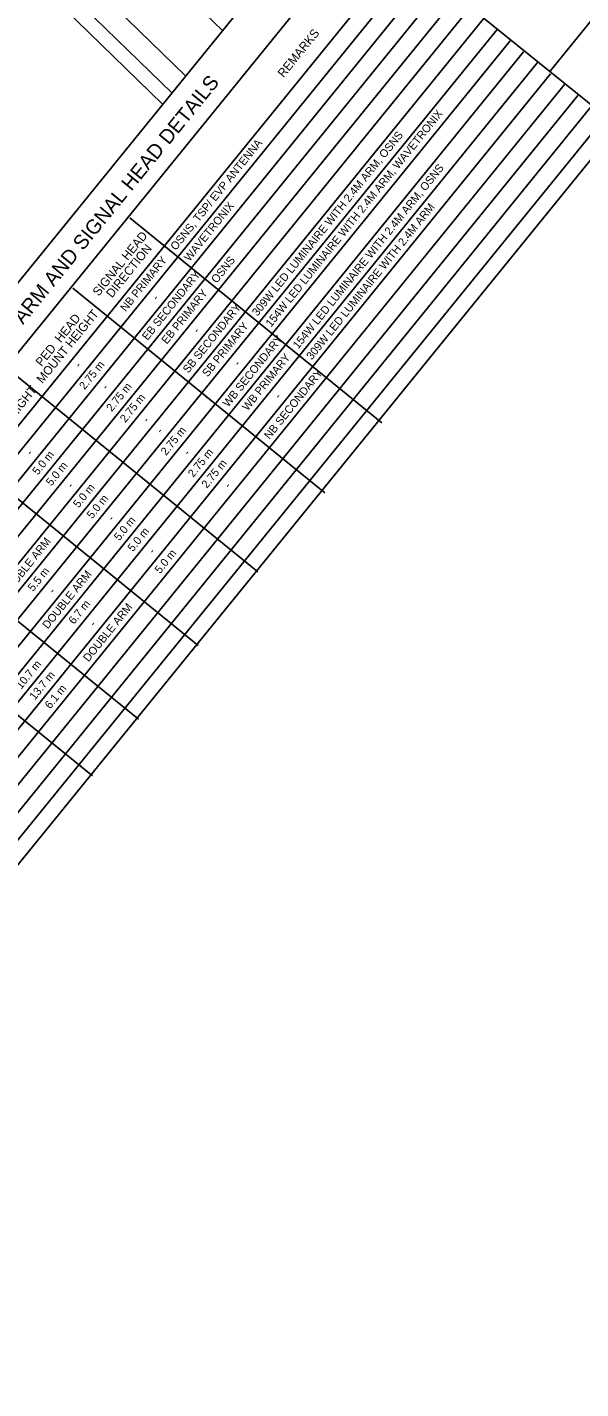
# Model space of a CAD drawing. Extents: x 592613 to 600223, y 4837996 to 4840103.
# Drawn here: x 593036.6 to 593074.7, y 4839186.1 to 4839279.7 of the extents above; entities that cross this region are included whole.
import ezdxf

# ---------------------------------------------------------------- set-up
doc = ezdxf.new("R2010")
doc.units = 0
for name, color, linetype in [('ENG_BORDER', 7, 'Continuous'), ('ENG_KILLSTRIP', 7, 'Continuous'), ('ENG_SIDEWALK', 7, 'Continuous'), ('ENG_TITLEBLOCK', 7, 'Continuous'), ('ENG_TX_TITLEBLOCK', 7, 'Continuous'), ('Level 31', 7, 'Continuous'), ('Level 54', 7, 'Continuous'), ('ROW_ENG_ROW', 7, 'Continuous')]:
    doc.layers.add(name, color=color, linetype=linetype)

msp = doc.modelspace()

# ---------------------------------------------------------------- linework, layer by layer
at = {"layer": 'ENG_BORDER'}
for p, q in [((593077.324, 4839272.823), (593057.566, 4839288.798)), ((593017.004, 4839234.009), (593059.952, 4839286.868)), ((593043.511, 4839266.633), (593043.622, 4839266.769))]:
    msp.add_line(p, q, dxfattribs=at)
msp.add_lwpolyline([(593006.685, 4839186.123), (593132.065, 4839340.435), (593027.682, 4839425.246)], dxfattribs=at)
at = {"layer": 'ENG_KILLSTRIP'}
msp.add_line((593050.039, 4839279.514), (593045.892, 4839283.543), dxfattribs=at)
at = {"layer": 'ENG_SIDEWALK'}
for p, q in [((593047.51, 4839276.395), (593025.434, 4839297.841)), ((593046.561, 4839275.225), (593024.799, 4839296.366))]:
    msp.add_line(p, q, dxfattribs=at)
at = {"layer": 'ENG_TITLEBLOCK'}
for p, q in [((593014.678, 4839235.899), (593087.391, 4839325.585)), ((593072.542, 4839276.692), (593083.341, 4839289.983))]:
    msp.add_line(p, q, dxfattribs=at)
at = {"layer": 'Level 31'}
for p, q in [((593019.478, 4839231.999), (593062.405, 4839284.832)), ((593022.481, 4839233.799), (593063.333, 4839284.078)), ((593021.335, 4839230.491), (593064.261, 4839283.324)), ((593022.263, 4839229.736), (593065.161, 4839282.536)), ((593023.19, 4839228.983), (593066.104, 4839281.799)), ((593024.118, 4839228.229), (593067.045, 4839281.062)), ((593025.046, 4839227.475), (593067.959, 4839280.291)), ((593025.974, 4839226.721), (593068.915, 4839279.571)), ((593026.902, 4839225.967), (593069.816, 4839278.782)), ((593027.831, 4839225.212), (593070.744, 4839278.029)), ((593028.759, 4839224.458), (593071.686, 4839277.292)), ((593029.686, 4839223.705), (593072.6, 4839276.52)), ((593030.615, 4839222.951), (593073.542, 4839275.784)), ((593031.543, 4839222.197), (593074.47, 4839275.029)), ((593032.471, 4839221.442), (593075.397, 4839274.276)), ((593033.399, 4839220.689), (593076.325, 4839273.521)), ((593060.998, 4839252.539), (593043.675, 4839266.614)), ((593057.072, 4839247.708), (593039.75, 4839261.782)), ((593052.48, 4839242.276), (593035.156, 4839256.35)), ((593048.369, 4839237.216), (593031.084, 4839251.26)), ((593044.257, 4839232.156), (593026.95, 4839246.219)), ((593041.095, 4839228.264), (593023.773, 4839242.338))]:
    msp.add_line(p, q, dxfattribs=at)
at = {"layer": 'Level 54'}
msp.add_line((593040.993, 4839228.347), (593023.773, 4839242.338), dxfattribs=at)
at = {"layer": 'ROW_ENG_ROW'}
msp.add_line((593045.929, 4839274.445), (593031.168, 4839288.785), dxfattribs=at)

# ---------------------------------------------------------------- texts
at = {"layer": 'ENG_TX_TITLEBLOCK'}
for s, height, rotation, p in [('REMARKS', 0.6, 50.9062, (593054.244, 4839276.225)), ('SIGNAL POLE, MAST ARM AND SIGNAL HEAD DETAILS', 1, 50.9062, (593027.702, 4839248.634)), ('154W LED LUMINAIRE WITH 2.4M ARM, WAVETRONIX', 0.55, 51.14583, (593053.379, 4839259.073)), ('309W LED LUMINAIRE WITH 2.4M ARM, OSNS', 0.55, 51.14583, (593052.444, 4839259.826)), ('OSNS, TSP/ EVP ANTENNA', 0.55, 51.14583, (593046.837, 4839264.343)), ('154W LED LUMINAIRE WITH 2.4M ARM, OSNS', 0.55, 51.14583, (593055.248, 4839257.568)), ('WAVETRONIX', 0.55, 51.14583, (593047.772, 4839263.59)), ('309W LED LUMINAIRE WITH 2.4M ARM', 0.55, 51.14583, (593056.182, 4839256.815)), ('SIGNAL HEAD', 0.6, 50.9062, (593041.527, 4839261.196)), ('DIRECTION', 0.6, 50.9062, (593042.445, 4839261.081)), ('NB PRIMARY', 0.55, 51.14583, (593043.391, 4839260.132)), ('OSNS', 0.55, 51.14583, (593049.641, 4839262.084)), ('EB SECONDARY', 0.55, 51.14583, (593044.885, 4839258.16)), ('-', 0.55, 51.14583, (593045.549, 4839260.898)), ('EB PRIMARY', 0.55, 51.14583, (593046.217, 4839257.901)), ('MOUNT HEIGHT', 0.6, 50.9062, (593037.663, 4839255.195)), ('SB SECONDARY', 0.55, 51.14583, (593047.688, 4839255.901)), ('PED  HEAD', 0.6, 50.9062, (593037.601, 4839256.365)), ('SB PRIMARY', 0.55, 51.14583, (593049.02, 4839255.642)), ('-', 0.55, 51.14583, (593048.353, 4839258.639)), ('WB SECONDARY', 0.55, 51.14583, (593050.434, 4839253.572)), ('WB PRIMARY', 0.55, 51.14583, (593051.767, 4839253.313)), ('-', 0.55, 51.14583, (593040.225, 4839256.261)), ('2.75 m', 0.55, 51.14583, (593040.562, 4839254.766)), ('-', 0.55, 51.14583, (593051.156, 4839256.381)), ('NB SECONDARY', 0.55, 51.14583, (593053.273, 4839251.357)), ('MOUNT HEIGHT', 0.6, 50.9062, (593033.415, 4839249.967)), ('-', 0.55, 51.14583, (593042.094, 4839254.755)), ('2.75 m', 0.55, 51.14583, (593042.431, 4839253.26)), ('2.75 m', 0.55, 51.14583, (593043.365, 4839252.508)), ('-', 0.55, 51.14583, (593053.96, 4839254.122)), ('-', 0.55, 51.14583, (593044.897, 4839252.497)), ('-', 0.55, 51.14583, (593045.832, 4839251.744)), ('2.75 m', 0.55, 51.14583, (593046.169, 4839250.249)), ('2.75 m', 0.55, 51.14583, (593048.038, 4839248.743)), ('-', 0.55, 51.14583, (593036.888, 4839250.246)), ('5.0 m', 0.55, 51.14583, (593037.345, 4839248.9)), ('5.0 m', 0.55, 51.14583, (593038.279, 4839248.148)), ('-', 0.55, 51.14583, (593047.701, 4839250.238)), ('2.75 m', 0.55, 51.14583, (593048.972, 4839247.991)), ('-', 0.55, 51.14583, (593039.692, 4839247.988)), ('5.0 m', 0.55, 51.14583, (593040.148, 4839246.642)), ('-', 0.55, 51.14583, (593050.504, 4839247.98)), ('5.0 m', 0.55, 51.14583, (593041.083, 4839245.889)), ('-', 0.55, 51.14583, (593042.495, 4839245.729)), ('5.0 m', 0.55, 51.14583, (593042.952, 4839244.384)), ('5.0 m', 0.55, 51.14583, (593043.886, 4839243.631)), ('DOUBLE ARM', 0.55, 51.14583, (593035.229, 4839240.578)), ('-', 0.55, 51.14583, (593045.299, 4839243.471)), ('5.0 m', 0.55, 51.14583, (593045.755, 4839242.125)), ('5.5 m', 0.55, 51.14583, (593037.028, 4839240.898)), ('DOUBLE ARM', 0.55, 51.14583, (593038.032, 4839238.32)), ('-', 0.55, 51.14583, (593038.44, 4839240.738)), ('6.7 m', 0.55, 51.14583, (593039.831, 4839238.64)), ('DOUBLE ARM', 0.55, 51.14583, (593040.836, 4839236.061)), ('-', 0.55, 51.14583, (593041.243, 4839238.48)), ('10.7 m', 0.55, 51.14583, (593036.21, 4839234.181)), ('13.7 m', 0.55, 51.14583, (593037.144, 4839233.428)), ('6.1 m', 0.55, 51.14583, (593038.199, 4839232.825))]:
    msp.add_text(s, height=height, rotation=rotation, dxfattribs=at).set_placement(p)

doc.saveas('drawing.dxf')
